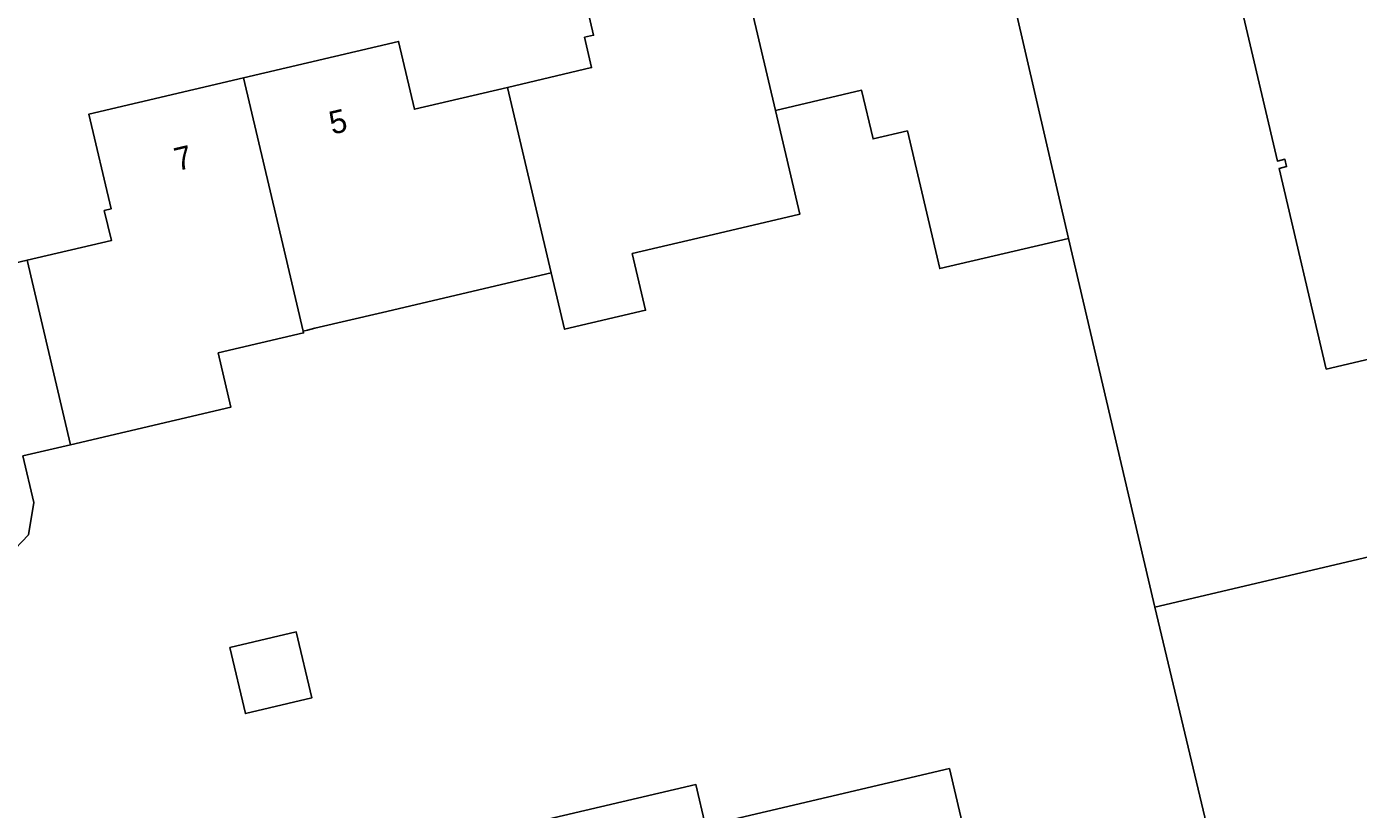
# Model space of a CAD drawing. Extents: x 157648 to 158502, y 379212 to 380938.
# Drawn here: x 158294.8 to 158352.6, y 380643.2 to 380677.1 of the extents above; entities that cross this region are included whole.
import ezdxf

# ---------------------------------------------------------------- set-up
doc = ezdxf.new("R2010")
doc.units = 0
for name, color, linetype in [('IMGEO_Erf', 7, 'Continuous'), ('IMGEO_Groenvoorziening', 7, 'Continuous'), ('IMGEO_Pand', 7, 'Continuous'), ('IMGEO_Pand_nummerreeks', 7, 'Continuous')]:
    doc.layers.add(name, color=color, linetype=linetype)

msp = doc.modelspace()

# ---------------------------------------------------------------- linework, layer by layer
at = {"layer": 'IMGEO_Erf'}
for points in [[(158345.272, 380687.413), (158349.054, 380671.311), (158349.376, 380671.387), (158349.451, 380671.066), (158349.129, 380670.99), (158351.17, 380662.296), (158371.954, 380667.177)], [(158290.91, 380666.085), (158294.848, 380667.01), (158298.495, 380667.867), (158298.19, 380669.166), (158298.481, 380669.235), (158297.517, 380673.339), (158304.231, 380674.916), (158310.947, 380676.493), (158311.638, 380673.553), (158315.674, 380674.501), (158319.32, 380675.357), (158319.012, 380676.669), (158319.402, 380676.761), (158318.439, 380680.864)], [(158343.739, 380651.985), (158342.596, 380656.853), (158339.988, 380667.96), (158334.415, 380666.651), (158333.014, 380672.615), (158331.521, 380672.265), (158331.026, 380674.376), (158327.286, 380673.498), (158328.342, 380669.003), (158324.596, 380668.123), (158321.08, 380667.297), (158321.655, 380664.846), (158318.144, 380664.021), (158317.563, 380666.471), (158310.25, 380664.753), (158307.317, 380664.064), (158306.995, 380663.988), (158306.809, 380663.945), (158306.828, 380663.864), (158303.128, 380662.996), (158303.678, 380660.653), (158296.726, 380659.02), (158294.658, 380658.535), (158295.132, 380656.517), (158294.9, 380655.123), (158294.054, 380654.218)], [(158348.517, 380631.909), (158343.739, 380651.985)], [(158316.5, 380642.576), (158323.841, 380644.3), (158324.263, 380642.505), (158334.831, 380644.988), (158338.49, 380629.41)]]:
    msp.add_lwpolyline(points, dxfattribs=at)
msp.add_lwpolyline([(158307.186, 380648.05), (158304.308, 380647.374), (158303.637, 380650.233), (158306.514, 380650.909)], close=True, dxfattribs=at)
at = {"layer": 'IMGEO_Groenvoorziening'}
msp.add_lwpolyline([(158403.279, 380647.612), (158400.091, 380665.22), (158381.763, 380660.915), (158343.739, 380651.985), (158348.517, 380631.909), (158348.666, 380631.281), (158350.43, 380631.698), (158350.304, 380632.233), (158353.678, 380633.026), (158354.469, 380629.66), (158354.229, 380629.604), (158354.441, 380628.708), (158355.423, 380628.938), (158404.084, 380640.327)], close=True, dxfattribs=at)
at = {"layer": 'IMGEO_Pand'}
for points in [[(158380.833, 380664.877), (158379.822, 380669.073), (158378.724, 380673.628), (158377.014, 380680.909), (158369.162, 380679.065), (158371.954, 380667.177), (158351.17, 380662.296), (158349.129, 380670.99), (158349.451, 380671.066), (158349.376, 380671.387), (158349.054, 380671.311), (158345.272, 380687.413), (158336.026, 380685.071), (158336.729, 380682.077), (158339.988, 380667.96), (158342.596, 380656.853), (158343.739, 380651.985), (158381.763, 380660.915)], [(158336.729, 380682.077), (158332.613, 380681.11), (158331.926, 380684.032), (158325.182, 380682.448), (158327.286, 380673.498), (158331.026, 380674.376), (158331.521, 380672.265), (158333.014, 380672.615), (158334.415, 380666.651), (158339.988, 380667.96)], [(158325.182, 380682.448), (158318.439, 380680.864), (158319.402, 380676.761), (158319.012, 380676.669), (158319.32, 380675.357), (158315.674, 380674.501), (158317.563, 380666.471), (158318.144, 380664.021), (158321.655, 380664.846), (158321.08, 380667.297), (158324.596, 380668.123), (158328.342, 380669.003), (158327.286, 380673.498)], [(158315.674, 380674.501), (158311.638, 380673.553), (158310.947, 380676.493), (158304.231, 380674.916), (158305.987, 380667.442), (158306.809, 380663.945), (158306.995, 380663.988), (158307.317, 380664.064), (158310.25, 380664.753), (158317.563, 380666.471)], [(158304.231, 380674.916), (158297.517, 380673.339), (158298.481, 380669.235), (158298.19, 380669.166), (158298.495, 380667.867), (158294.848, 380667.01), (158296.726, 380659.02), (158303.678, 380660.653), (158303.128, 380662.996), (158306.828, 380663.864), (158306.809, 380663.945), (158305.987, 380667.442)], [(158285.378, 380659.026), (158285.973, 380656.495), (158289.429, 380657.307), (158289.99, 380654.918), (158290.926, 380654.044), (158292.32, 380653.811), (158294.054, 380654.218), (158294.9, 380655.123), (158295.132, 380656.517), (158294.658, 380658.535), (158296.726, 380659.02), (158294.848, 380667.01), (158290.91, 380666.085), (158290.21, 380669.064), (158283.396, 380667.463)], [(158304.308, 380647.374), (158307.186, 380648.05), (158306.514, 380650.909), (158303.637, 380650.233)], [(158316.97, 380640.574), (158317.497, 380638.329), (158319.465, 380629.95), (158326.215, 380631.535), (158325.265, 380635.583), (158328.37, 380636.312), (158329.509, 380631.465), (158330.679, 380631.736), (158331.494, 380628.271), (158330.324, 380627.996), (158330.427, 380627.557), (158331.691, 380627.813), (158338.49, 380629.41), (158334.831, 380644.988), (158324.263, 380642.505), (158323.841, 380644.3), (158316.5, 380642.576)]]:
    msp.add_lwpolyline(points, close=True, dxfattribs=at)

# ---------------------------------------------------------------- texts
at = {"layer": 'IMGEO_Pand_nummerreeks'}
for s, p in [('5', (158308.071, 380672.448)), ('7', (158301.356, 380670.871))]:
    msp.add_text(s, height=1, rotation=13.21814, dxfattribs=at).set_placement(p)

doc.saveas('drawing.dxf')
